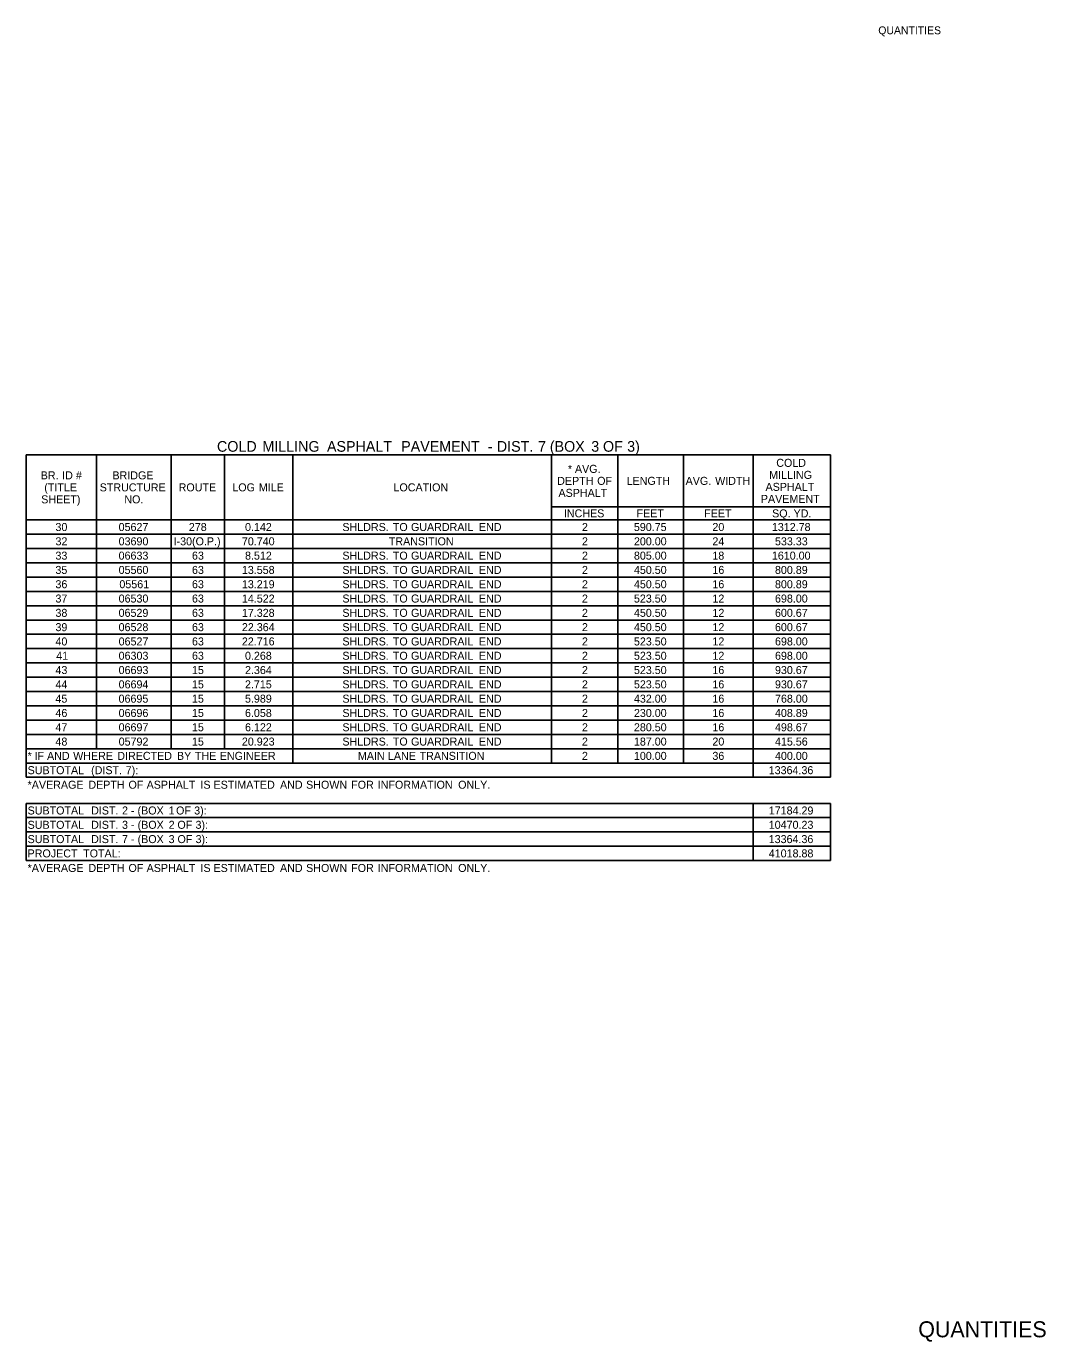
# Model space of a CAD drawing. Extents: x 544250 to 1930787, y -1948365 to 596640.
# Drawn here: x 548824 to 549589, y -1948344 to -1947358 of the extents above; entities that cross this region are included whole.
import ezdxf

# ---------------------------------------------------------------- set-up
doc = ezdxf.new("R2010")
doc.units = 0
for name, color, linetype in [('Default', 7, 'Continuous'), ('R_Border', 7, 'Continuous'), ('R_Border Prem', 7, 'Continuous')]:
    doc.layers.add(name, color=color, linetype=linetype)

msp = doc.modelspace()

# ---------------------------------------------------------------- linework, layer by layer
at = {"layer": 'Default'}
for p, q in [((548824.31, -1947679.28), (549427.34, -1947679.28)), ((548824.31, -1947679.28), (549427.34, -1947679.28)), ((548824.31, -1947921.08), (548824.31, -1947679.28)), ((548824.31, -1947921.08), (548824.31, -1947679.28)), ((548876.96, -1947899.63), (548876.96, -1947679.28)), ((548933.02, -1947899.63), (548933.02, -1947679.28)), ((548972.99, -1947899.63), (548972.99, -1947679.28)), ((549024.18, -1947910.36), (549024.18, -1947679.28)), ((549218.21, -1947910.36), (549218.21, -1947679.28)), ((549267.93, -1947910.36), (549267.93, -1947679.28)), ((549317.17, -1947910.36), (549317.17, -1947679.28)), ((549369.33, -1947921.08), (549369.33, -1947679.28)), ((549427.34, -1947921.08), (549427.34, -1947679.28)), ((549218.21, -1947718.28), (549317.17, -1947718.28)), ((549218.21, -1947718.28), (549267.93, -1947718.28)), ((549267.93, -1947718.28), (549427.34, -1947718.28)), ((549317.17, -1947728.03), (549317.17, -1947718.28)), ((548824.31, -1947728.03), (549427.34, -1947728.03)), ((549369.33, -1947728.03), (549427.34, -1947728.03)), ((548824.31, -1947738.76), (549427.34, -1947738.76)), ((548824.31, -1947749.48), (549369.33, -1947749.48)), ((549369.33, -1947749.48), (549427.34, -1947749.48)), ((548824.31, -1947760.21), (549427.34, -1947760.21)), ((548824.31, -1947770.93), (549427.34, -1947770.93)), ((549369.33, -1947770.93), (549427.34, -1947770.93)), ((548824.31, -1947781.66), (549427.34, -1947781.66)), ((548824.31, -1947792.38), (549427.34, -1947792.38)), ((549369.33, -1947792.38), (549427.34, -1947792.38)), ((548824.31, -1947803.11), (549427.34, -1947803.11)), ((548824.31, -1947813.83), (549427.34, -1947813.83)), ((549369.33, -1947813.83), (549427.34, -1947813.83)), ((548824.31, -1947824.56), (549427.34, -1947824.56)), ((548824.31, -1947835.28), (549427.34, -1947835.28)), ((548824.31, -1947846.01), (549427.34, -1947846.01)), ((549369.33, -1947846.01), (549427.34, -1947846.01)), ((548824.31, -1947856.73), (549427.34, -1947856.73)), ((548824.31, -1947867.46), (549427.34, -1947867.46)), ((549369.33, -1947867.46), (549427.34, -1947867.46)), ((548824.31, -1947878.18), (549427.34, -1947878.18)), ((548824.31, -1947888.91), (549427.34, -1947888.91)), ((548824.31, -1947899.63), (549427.34, -1947899.63)), ((549369.33, -1947899.63), (549427.34, -1947899.63)), ((548824.31, -1947910.36), (549427.34, -1947910.36)), ((548824.31, -1947921.08), (549427.34, -1947921.08)), ((548824.31, -1947940.58), (549427.34, -1947940.58)), ((548824.31, -1947940.58), (549427.34, -1947940.58)), ((548824.31, -1947983.48), (548824.31, -1947940.58)), ((548824.31, -1947983.48), (548824.31, -1947940.58)), ((549369.33, -1947983.48), (549369.33, -1947940.58)), ((549427.34, -1947983.48), (549427.34, -1947940.58)), ((548824.31, -1947951.31), (549427.34, -1947951.31)), ((548824.31, -1947962.03), (549427.34, -1947962.03)), ((548824.31, -1947972.76), (549427.34, -1947972.76)), ((548824.31, -1947983.48), (549427.34, -1947983.48))]:
    msp.add_line(p, q, dxfattribs=at)

# ---------------------------------------------------------------- texts
for s, height, p in [('COLD', 8, (548967.3, -1947676.94)), (' MILLING', 8, (548998.42, -1947676.94)), (' ASPHALT', 8, (549046.79, -1947676.94)), (' PAVEMENT', 8, (549102.45, -1947676.94)), (' -', 8, (549167.44, -1947676.94)), (' DIST.', 8, (549174.18, -1947676.94)), (' 7', 8, (549205.09, -1947676.94)), (' (BOX', 8, (549213.91, -1947676.94)), (' 3', 8, (549244.95, -1947676.94)), (' OF', 8, (549253.78, -1947676.94)), (' 3)', 8, (549271.89, -1947676.94)), ('COLD', 6, (549386.67, -1947688.28)), ('BR.', 6, (548835.11, -1947697.66)), (' ID', 6, (548848.97, -1947697.66)), (' #', 6, (548859.26, -1947697.66)), ('BRIDGE', 6, (548888.89, -1947697.66)), ('*', 6, (549230.4, -1947692.78)), (' AVG.', 6, (549233.48, -1947692.78)), ('MILLING', 6, (549381.36, -1947697.28)), ('(TITLE', 6, (548837.8, -1947706.66)), ('STRUCTURE', 6, (548879.34, -1947706.66)), ('ROUTE', 6, (548938.54, -1947706.66)), ('LOG', 6, (548978.79, -1947706.66)), (' MILE', 6, (548996.45, -1947706.66)), ('LOCATION', 6, (549099.64, -1947706.66)), ('DEPTH', 6, (549222.39, -1947701.78)), (' OF', 6, (549250.16, -1947701.78)), ('LENGTH', 6, (549274.47, -1947701.78)), ('AVG.', 6, (549318.71, -1947701.78)), (' WIDTH', 6, (549338.63, -1947701.78)), ('ASPHALT', 6, (549378.63, -1947706.28)), ('SHEET)', 6, (548835.48, -1947715.66)), ('NO.', 6, (548897.82, -1947715.66)), ('ASPHALT', 6, (549223.36, -1947710.78)), ('PAVEMENT', 6, (549375.13, -1947715.28)), ('INCHES', 6, (549227.43, -1947726.16)), ('FEET', 6, (549281.92, -1947726.16)), ('FEET', 6, (549332.62, -1947726.16)), ('SQ.', 6, (549383.54, -1947726.16)), (' YD.', 6, (549397.41, -1947726.16)), ('30', 6, (548846.17, -1947736.39)), ('05627', 6, (548893.53, -1947736.39)), ('278', 6, (548946.2, -1947736.39)), ('0.142', 6, (548988.32, -1947736.39)), ('SHLDRS.', 6, (549061.33, -1947736.39)), (' TO', 6, (549096.93, -1947736.39)), (' GUARDRAIL', 6, (549110.53, -1947736.39)), (' END', 6, (549161.48, -1947736.39)), ('2', 6, (549240.96, -1947736.39)), ('590.75', 6, (549279.9, -1947736.39)), ('20', 6, (549338.79, -1947736.39)), ('1312.78', 6, (549383.38, -1947736.39)), ('32', 6, (548846.19, -1947747.12)), ('03690', 6, (548893.54, -1947747.12)), ('I-30(O.P.)', 6, (548934.76, -1947747.12)), ('70.740', 6, (548985.97, -1947747.12)), ('TRANSITION', 6, (549096.15, -1947747.12)), ('2', 6, (549240.96, -1947747.12)), ('200.00', 6, (549279.94, -1947747.12)), ('24', 6, (549338.79, -1947747.12)), ('533.33', 6, (549385.71, -1947747.12)), ('33', 6, (548846.16, -1947757.84)), ('06633', 6, (548893.53, -1947757.84)), ('63', 6, (548948.54, -1947757.84)), ('8.512', 6, (548988.32, -1947757.84)), ('SHLDRS.', 6, (549061.33, -1947757.84)), (' TO', 6, (549096.93, -1947757.84)), (' GUARDRAIL', 6, (549110.53, -1947757.84)), (' END', 6, (549161.48, -1947757.84)), ('2', 6, (549240.96, -1947757.84)), ('805.00', 6, (549279.94, -1947757.84)), ('18', 6, (549338.77, -1947757.84)), ('1610.00', 6, (549383.39, -1947757.84)), ('35', 6, (548846.14, -1947768.57)), ('05560', 6, (548893.54, -1947768.57)), ('63', 6, (548948.54, -1947768.57)), ('13.558', 6, (548985.96, -1947768.57)), ('SHLDRS.', 6, (549061.33, -1947768.57)), (' TO', 6, (549096.93, -1947768.57)), (' GUARDRAIL', 6, (549110.53, -1947768.57)), (' END', 6, (549161.48, -1947768.57)), ('2', 6, (549240.96, -1947768.57)), ('450.50', 6, (549279.94, -1947768.57)), ('16', 6, (549338.78, -1947768.57)), ('800.89', 6, (549385.71, -1947768.57)), ('36', 6, (548846.16, -1947779.29)), ('05561', 6, (548894.11, -1947779.29)), ('63', 6, (548948.54, -1947779.29)), ('13.219', 6, (548985.96, -1947779.29)), ('SHLDRS.', 6, (549061.33, -1947779.29)), (' TO', 6, (549096.93, -1947779.29)), (' GUARDRAIL', 6, (549110.53, -1947779.29)), (' END', 6, (549161.48, -1947779.29)), ('2', 6, (549240.96, -1947779.29)), ('450.50', 6, (549279.94, -1947779.29)), ('16', 6, (549338.78, -1947779.29)), ('800.89', 6, (549385.71, -1947779.29)), ('37', 6, (548846.16, -1947790.02)), ('06530', 6, (548893.54, -1947790.02)), ('63', 6, (548948.54, -1947790.02)), ('14.522', 6, (548985.99, -1947790.02)), ('SHLDRS.', 6, (549061.33, -1947790.02)), (' TO', 6, (549096.93, -1947790.02)), (' GUARDRAIL', 6, (549110.53, -1947790.02)), (' END', 6, (549161.48, -1947790.02)), ('2', 6, (549240.96, -1947790.02)), ('523.50', 6, (549279.94, -1947790.02)), ('12', 6, (549338.81, -1947790.02)), ('698.00', 6, (549385.72, -1947790.02)), ('38', 6, (548846.16, -1947800.74)), ('06529', 6, (548893.52, -1947800.74)), ('63', 6, (548948.54, -1947800.74)), ('17.328', 6, (548985.96, -1947800.74)), ('SHLDRS.', 6, (549061.33, -1947800.74)), (' TO', 6, (549096.93, -1947800.74)), (' GUARDRAIL', 6, (549110.53, -1947800.74)), (' END', 6, (549161.48, -1947800.74)), ('2', 6, (549240.96, -1947800.74)), ('450.50', 6, (549279.94, -1947800.74)), ('12', 6, (549338.81, -1947800.74)), ('600.67', 6, (549385.71, -1947800.74)), ('39', 6, (548846.16, -1947811.47)), ('06528', 6, (548893.52, -1947811.47)), ('63', 6, (548948.54, -1947811.47)), ('22.364', 6, (548985.98, -1947811.47)), ('SHLDRS.', 6, (549061.33, -1947811.47)), (' TO', 6, (549096.93, -1947811.47)), (' GUARDRAIL', 6, (549110.53, -1947811.47)), (' END', 6, (549161.48, -1947811.47)), ('2', 6, (549240.96, -1947811.47)), ('450.50', 6, (549279.94, -1947811.47)), ('12', 6, (549338.81, -1947811.47)), ('600.67', 6, (549385.71, -1947811.47)), ('40', 6, (548846.17, -1947822.19)), ('06527', 6, (548893.53, -1947822.19)), ('63', 6, (548948.54, -1947822.19)), ('22.716', 6, (548985.96, -1947822.19)), ('SHLDRS.', 6, (549061.33, -1947822.19)), (' TO', 6, (549096.93, -1947822.19)), (' GUARDRAIL', 6, (549110.53, -1947822.19)), (' END', 6, (549161.48, -1947822.19)), ('2', 6, (549240.96, -1947822.19)), ('523.50', 6, (549279.94, -1947822.19)), ('12', 6, (549338.81, -1947822.19)), ('698.00', 6, (549385.72, -1947822.19)), ('41', 6, (548846.74, -1947832.92)), ('06303', 6, (548893.53, -1947832.92)), ('63', 6, (548948.54, -1947832.92)), ('0.268', 6, (548988.29, -1947832.92)), ('SHLDRS.', 6, (549061.33, -1947832.92)), (' TO', 6, (549096.93, -1947832.92)), (' GUARDRAIL', 6, (549110.53, -1947832.92)), (' END', 6, (549161.48, -1947832.92)), ('2', 6, (549240.96, -1947832.92)), ('523.50', 6, (549279.94, -1947832.92)), ('12', 6, (549338.81, -1947832.92)), ('698.00', 6, (549385.72, -1947832.92)), ('43', 6, (548846.16, -1947843.64)), ('06693', 6, (548893.53, -1947843.64)), ('15', 6, (548948.51, -1947843.64)), ('2.364', 6, (548988.31, -1947843.64)), ('SHLDRS.', 6, (549061.33, -1947843.64)), (' TO', 6, (549096.93, -1947843.64)), (' GUARDRAIL', 6, (549110.53, -1947843.64)), (' END', 6, (549161.48, -1947843.64)), ('2', 6, (549240.96, -1947843.64)), ('523.50', 6, (549279.94, -1947843.64)), ('16', 6, (549338.78, -1947843.64)), ('930.67', 6, (549385.71, -1947843.64)), ('44', 6, (548846.17, -1947854.37)), ('06694', 6, (548893.54, -1947854.37)), ('15', 6, (548948.51, -1947854.37)), ('2.715', 6, (548988.27, -1947854.37)), ('SHLDRS.', 6, (549061.33, -1947854.37)), (' TO', 6, (549096.93, -1947854.37)), (' GUARDRAIL', 6, (549110.53, -1947854.37)), (' END', 6, (549161.48, -1947854.37)), ('2', 6, (549240.96, -1947854.37)), ('523.50', 6, (549279.94, -1947854.37)), ('16', 6, (549338.78, -1947854.37)), ('930.67', 6, (549385.71, -1947854.37)), ('45', 6, (548846.14, -1947865.09)), ('06695', 6, (548893.5, -1947865.09)), ('15', 6, (548948.51, -1947865.09)), ('5.989', 6, (548988.29, -1947865.09)), ('SHLDRS.', 6, (549061.33, -1947865.09)), (' TO', 6, (549096.93, -1947865.09)), (' GUARDRAIL', 6, (549110.53, -1947865.09)), (' END', 6, (549161.48, -1947865.09)), ('2', 6, (549240.96, -1947865.09)), ('432.00', 6, (549279.94, -1947865.09)), ('16', 6, (549338.78, -1947865.09)), ('768.00', 6, (549385.72, -1947865.09)), ('46', 6, (548846.16, -1947875.82)), ('06696', 6, (548893.53, -1947875.82)), ('15', 6, (548948.51, -1947875.82)), ('6.058', 6, (548988.29, -1947875.82)), ('SHLDRS.', 6, (549061.33, -1947875.82)), (' TO', 6, (549096.93, -1947875.82)), (' GUARDRAIL', 6, (549110.53, -1947875.82)), (' END', 6, (549161.48, -1947875.82)), ('2', 6, (549240.96, -1947875.82)), ('230.00', 6, (549279.94, -1947875.82)), ('16', 6, (549338.78, -1947875.82)), ('408.89', 6, (549385.71, -1947875.82)), ('47', 6, (548846.16, -1947886.54)), ('06697', 6, (548893.53, -1947886.54)), ('15', 6, (548948.51, -1947886.54)), ('6.122', 6, (548988.32, -1947886.54)), ('SHLDRS.', 6, (549061.33, -1947886.54)), (' TO', 6, (549096.93, -1947886.54)), (' GUARDRAIL', 6, (549110.53, -1947886.54)), (' END', 6, (549161.48, -1947886.54)), ('2', 6, (549240.96, -1947886.54)), ('280.50', 6, (549279.94, -1947886.54)), ('16', 6, (549338.78, -1947886.54)), ('498.67', 6, (549385.71, -1947886.54)), ('48', 6, (548846.16, -1947897.27)), ('05792', 6, (548893.56, -1947897.27)), ('15', 6, (548948.51, -1947897.27)), ('20.923', 6, (548985.96, -1947897.27)), ('SHLDRS.', 6, (549061.33, -1947897.27)), (' TO', 6, (549096.93, -1947897.27)), (' GUARDRAIL', 6, (549110.53, -1947897.27)), (' END', 6, (549161.48, -1947897.27)), ('2', 6, (549240.96, -1947897.27)), ('187.00', 6, (549279.94, -1947897.27)), ('20', 6, (549338.79, -1947897.27)), ('415.56', 6, (549385.71, -1947897.27)), ('*', 6, (548825.28, -1947907.99)), (' IF', 6, (548828.25, -1947907.99)), (' AND', 6, (548837.64, -1947907.99)), (' WHERE', 6, (548857.22, -1947907.99)), (' DIRECTED', 6, (548890.31, -1947907.99)), (' BY', 6, (548935.05, -1947907.99)), (' THE', 6, (548948.5, -1947907.99)), (' ENGINEER', 6, (548967.14, -1947907.99)), ('MAIN', 6, (549072.96, -1947907.99)), (' LANE', 6, (549093.23, -1947907.99)), (' TRANSITION', 6, (549117.01, -1947907.99)), ('2', 6, (549240.96, -1947907.99)), ('100.00', 6, (549279.94, -1947907.99)), ('36', 6, (549338.78, -1947907.99)), ('400.00', 6, (549385.72, -1947907.99)), ('SUBTOTAL', 6, (548825.28, -1947918.72)), (' (DIST.', 6, (548870.67, -1947918.72)), (' 7):', 6, (548896.64, -1947918.72)), ('13364.36', 6, (549381.01, -1947918.72)), ('*AVERAGE', 6, (548825.28, -1947929.63)), (' DEPTH', 6, (548868.63, -1947929.63)), (' OF', 6, (548898.7, -1947929.63)), (' ASPHALT', 6, (548912.29, -1947929.63)), (' IS', 6, (548952.66, -1947929.63)), (' ESTIMATED', 6, (548962.47, -1947929.63)), (' AND', 6, (549012.33, -1947929.63)), (' SHOWN', 6, (549031.91, -1947929.63)), (' FOR', 6, (549065.69, -1947929.63)), (' INFORMATION', 6, (549085.6, -1947929.63)), (' ONLY.', 6, (549145.92, -1947929.63)), ('SUBTOTAL', 6, (548825.28, -1947948.94)), (' DIST.', 6, (548870.67, -1947948.94)), (' 2', 6, (548893.85, -1947948.94)), (' -', 6, (548900.42, -1947948.94)), (' (BOX', 6, (548905.48, -1947948.94)), (' 1', 6, (548928.75, -1947948.94)), (' OF', 6, (548934.38, -1947948.94)), (' 3):', 6, (548947.96, -1947948.94)), ('17184.29', 6, (549381.06, -1947948.94)), ('SUBTOTAL', 6, (548825.28, -1947959.67)), (' DIST.', 6, (548870.67, -1947959.67)), (' 3', 6, (548893.85, -1947959.67)), (' -', 6, (548900.48, -1947959.67)), (' (BOX', 6, (548905.54, -1947959.67)), (' 2', 6, (548928.81, -1947959.67)), (' OF', 6, (548935.38, -1947959.67)), (' 3):', 6, (548948.96, -1947959.67)), ('10470.23', 6, (549381.04, -1947959.67)), ('SUBTOTAL', 6, (548825.28, -1947970.39)), (' DIST.', 6, (548870.67, -1947970.39)), (' 7', 6, (548893.85, -1947970.39)), (' -', 6, (548900.47, -1947970.39)), (' (BOX', 6, (548905.53, -1947970.39)), (' 3', 6, (548928.8, -1947970.39)), (' OF', 6, (548935.43, -1947970.39)), (' 3):', 6, (548949.01, -1947970.39)), ('13364.36', 6, (549381.01, -1947970.39)), ('PROJECT', 6, (548825.28, -1947981.12)), (' TOTAL:', 6, (548864.71, -1947981.12)), ('41018.88', 6, (549381.05, -1947981.12)), ('*AVERAGE', 6, (548825.28, -1947992.03)), (' DEPTH', 6, (548868.63, -1947992.03)), (' OF', 6, (548898.7, -1947992.03)), (' ASPHALT', 6, (548912.29, -1947992.03)), (' IS', 6, (548952.66, -1947992.03)), (' ESTIMATED', 6, (548962.47, -1947992.03)), (' AND', 6, (549012.33, -1947992.03)), (' SHOWN', 6, (549031.91, -1947992.03)), (' FOR', 6, (549065.69, -1947992.03)), (' INFORMATION', 6, (549085.6, -1947992.03)), (' ONLY.', 6, (549145.92, -1947992.03))]:
    msp.add_text(s, height=height, dxfattribs=at).set_placement(p)
at = {"layer": 'R_Border'}
msp.add_text('QUANTITIES', height=12, rotation=360, dxfattribs=at).set_placement((549493.16, -1948340.95))
at = {"layer": 'R_Border Prem'}
msp.add_text('QUANTITIES', height=5.862, rotation=360, dxfattribs=at).set_placement((549463.18, -1947363.9))

doc.saveas('drawing.dxf')
